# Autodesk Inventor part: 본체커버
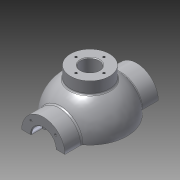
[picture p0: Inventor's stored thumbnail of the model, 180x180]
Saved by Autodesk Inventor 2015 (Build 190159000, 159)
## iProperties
Created: 2015-12
Part Number: 본체커버
Material: 알루미늄 6061
Document SubType Name: Modeling
Designer: mduedu
Density: 2.71 g/cm^3
Mass: 547.271 g
Surface Area: 428.16 cm^2
Volume: 201.945 cm^3
Appearance: 알루미늄 - 평지
Author: mduedu
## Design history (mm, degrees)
sketch "스케치1"
  geometry: L1 (-53, 0)-(53, 0); A1 r 53 centre (0, 0) between (53, 0) and (-53, 0); 2 further points
  constraints: 2 coincident, 2 end point, 2 point on circle, 1 centre point, 1 horizontal, 1 midpoint
  dimensions: "d0" = 53 radius of A1
revolve "회전1" sketch "스케치1" stored, may be unused: angle "d2" = 90 deg
feature "쉘1" dims "d11" = 10
node "작업 평면1"
sketch "스케치2"
  geometry: C1 r 31 at (0, 0); 1 further point
  constraints: 1 centre point, 1 coincident
  dimensions: "d4" = 62 diameter of C1
extrude "돌출1" join sketch "스케치2" stored distance "d5" = 10; taper "d6" = 0 deg
hole "구멍1" diameter "d14" = 35; stored, may be unused: countersink angle "d18" = 90 deg, drill point angle "d20" = 0 deg; dims "d12" = 10, "d13" = 10, "d15" = 6, "d16" = 4, "d17" = 2, "d19" = 16
hole "구멍2" diameter "d23" = 27; stored, may be unused: countersink angle "d27" = 90 deg, drill point angle "d29" = 0 deg; dims "d21" = 10, "d22" = 10, "d24" = 6, "d25" = 4, "d26" = 2, "d28" = 16
fillet "모깎기1" dims "d30" = 0.3
chamfer "모따기1" distance "d40" = 1; stored, may be unused: second distance "d41" = 2, angle "d42" = 45 deg
sketch "스케치4"
  geometry: L1 (0, 0)-(0, -25); L2 (0, 0)-(-17.678, -17.678); A1 r 25 centre (0, 0) between (-17.678, -17.678) and (0, -25); 1 further point
  constraints: 4 end point, 2 point on circle, 1 centre point, 1 coincident, 1 vertical
  dimensions: "d43" = 50 diameter of A1; "d47" = 45 deg angle of L1 L2
hole "구멍4" sketch "스케치4" at (-17.678, -17.678) diameter "d49" = 3.242; stored, may be unused: countersink angle "d53" = 90 deg, drill point angle "d55" = 118 deg; dims "d50" = 11, "d51" = 4, "d52" = 2, "d54" = 13
node "작업 평면3"
sketch "스케치6"
  geometry: C1 r 65 at (0, 0); 1 further point
  constraints: 1 centre point, 1 coincident
  dimensions: "d78" = 130 diameter of C1
extrude "돌출3" join sketch "스케치6" distance "d80" = 10; taper "d81" = 0 deg
sketch "스케치7"
  geometry: C1 r 20 at (0, 0); 1 further point
  constraints: 1 centre point, 1 coincident
  dimensions: "d82" = 40 diameter of C1
extrude "돌출4" join sketch "스케치7" stored distance "d84" = 10; taper "d85" = 0 deg
sketch "스케치8"
  geometry: 2 further points
  constraints: 1 coincident
hole "구멍6" sketch "스케치8" at (0, 0) diameter "d86" = 20; stored, may be unused: countersink angle "d90" = 90 deg, drill point angle "d92" = 118 deg; dims "d87" = 7, "d88" = 40, "d89" = 5, "d91" = 10
fillet "모깎기2" dims "d93" = 0.3
sketch "스케치9"
  geometry: L1 (65, -75)-(-65, -75) reference; L2 (-45, -75)-(-38.245, -36.692); A1 r 53 centre (0, 0) between (42.988, 31) and (42.988, -31) reference; 1 further point
  constraints: 2 end point, 1 point on circle, 1 point on line
  dimensions: "d94" = 45 horizontal distance of L2.start point (0, 0); "d95" = 80 deg angle of L2 L1
feature "리브1" sketch "스케치9" dims "d96" = 1, "d97" = 8, "d98" = 0, "d99" = 0, "d100" = 1, "d101" = 1
sketch "스케치10"
  geometry: L1 (0, 0)-(0, -55); L2 (0, 0)-(-38.891, -38.891); A1 r 55 centre (0, 0) between (0, -55) and (-38.891, -38.891); 2 further points
  constraints: 4 end point, 2 coincident, 2 point on circle, 1 centre point, 1 vertical
  dimensions: "d105" = 110 diameter of A1; "d107" = 45 deg angle of L1 L2
hole "구멍7" sketch "스케치10" at (-38.891, -38.891) diameter "d109" = 10; stored, may be unused: countersink angle "d113" = 90 deg, drill point angle "d115" = 118 deg; dims "d110" = 7, "d111" = 40, "d112" = 5, "d114" = 10
fillet "모깎기3" dims "d120" = 3
fillet "모깎기4" dims "d121" = 3, "d122" = 3
fillet "모깎기5" dims "d123" = 3
fillet "모깎기6" dims "d124" = 3
sketch "스케치11"
  geometry: C1 r 5 at (-38.891, 38.891) reference; C2 r 5 at (38.891, 38.891) reference; C3 r 5 at (38.891, -38.891) reference; C4 r 5 at (-38.891, -38.891) reference; C5 r 20 at (0, 0) reference; C6 r 65 at (0, 0) reference; 1 further point
  constraints: 3 other
feature "엠보싱1" sketch "스케치11" dims "d125" = 0.5, "d126" = 0
sketch "스케치12"
  geometry: L1 (0, 100)-(0, -100); L2 (0, 100)-(-150, 100); L3 (-150, 100)-(-150, -100); L4 (-150, -100)-(0, -100); 2 further points
  constraints: 8 end point, 3 perpendicular, 1 coincident, 1 midpoint, 1 vertical
  dimensions: "d127" = 200 distance of L2.end L3.end; "d129" = 150 distance of L3.end L1.end
extrude "돌출5" cut sketch "스케치12" stored distance "d130" = 10; taper "d131" = 0 deg
node "작업 평면4"
sketch "스케치16"
  geometry: C1 r 28 at (0, 0); 1 further point
  constraints: 1 centre point, 1 coincident
  dimensions: "d148" = 56 diameter of C1
extrude "돌출9" join sketch "스케치16" stored distance "d150" = 5; taper "d151" = 0 deg
hole "구멍8" diameter "d154" = 26; stored, may be unused: countersink angle "d158" = 90 deg, drill point angle "d160" = 118 deg; dims "d152" = 10, "d153" = 10, "d155" = 6, "d156" = 4, "d157" = 2, "d159" = 8
sketch "스케치17" dims "d161" = 40
  geometry: 3 further points
  constraints: 2 vertical alignment, 1 coincident, 2 other
hole "구멍9" sketch "스케치17" at (0, 20) diameter "d163" = 3.242; stored, may be unused: countersink angle "d167" = 90 deg, drill point angle "d169" = 118 deg; dims "d164" = 8, "d165" = 4, "d166" = 2, "d168" = 10
fillet "모깎기11" dims "d173" = 3
chamfer "모따기2" distance "d174" = 1; stored, may be unused: second distance "d175" = 2, angle "d176" = 45 deg
node "솔리드1"
mirror "대칭1"
mirror "대칭2"
pattern_circular "원형 패턴1" dims angle "d57" = 360 deg
mirror "대칭3"
pattern_circular "원형 패턴3" dims angle "d103" = 360 deg
pattern_circular "원형 패턴4" dims "d40" = 1, angle "d118" = 360 deg
pattern_circular "원형 패턴5" dims angle "d171" = 360 deg
node "투영된 루프1"
other parameters: "d3" = 67, "d77" = -85, "d147" = 62
